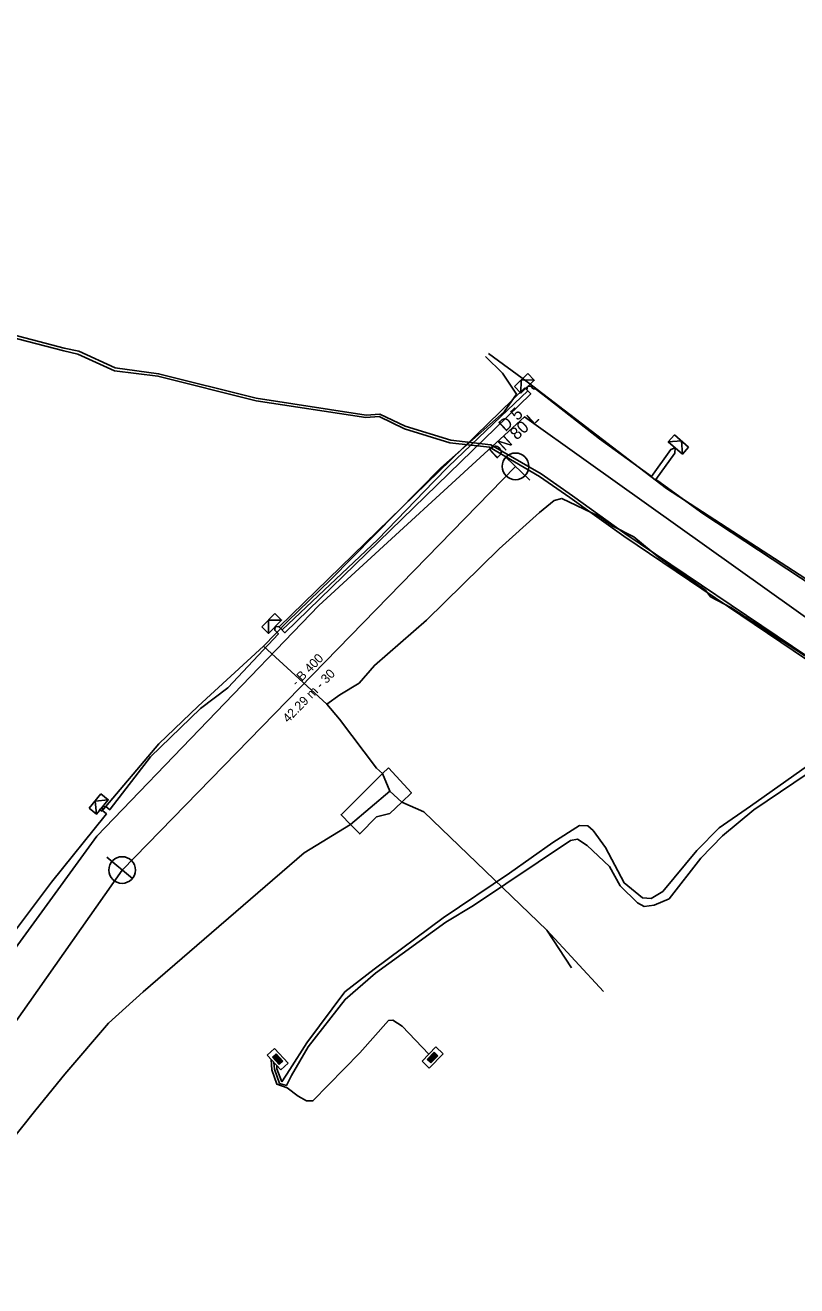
# Model space of a CAD drawing. Extents: x -600636 to -600148, y -1203980 to -1203569.
# Drawn here: x -600483.1 to -600425.2, y -1203834.8 to -1203740.1 of the extents above; entities that cross this region are included whole.
import ezdxf

# ---------------------------------------------------------------- set-up
doc = ezdxf.new("R2010")
doc.units = 0
for name, color, linetype in [('Cetin kolektor kabelovod', 7, 'Continuous'), ('Cetin nezaměřený', 7, 'Continuous'), ('Cetin NN přípojka', 7, 'Continuous'), ('Cetin zam průběh', 7, 'Continuous'), ('EON objekty', 7, 'Continuous'), ('EON podzemní NN', 7, 'Continuous'), ('EON podzemní VN', 7, 'Continuous'), ('Implicitní', 7, 'Continuous'), ('VaK Břeclav_kanalizace', 7, 'Continuous'), ('VaK Břeclav_kanalizace_popis', 7, 'Continuous'), ('Vak Břeclav_vodovod', 7, 'Continuous'), ('Vak Břeclav_vodovod_popis', 7, 'Continuous'), ('Vrstva 9', 7, 'Continuous')]:
    doc.layers.add(name, color=color, linetype=linetype)

# ---------------------------------------------------------------- blocks, each defined once
blk = doc.blocks.new('NN630')
at = {"layer": 'Vrstva 9'}
for points in [[(-0.003, -0.7), (-0.703, 0)], [(-0.703, -0.7), (-0.703, 0), (0.697, 0), (0.697, -0.7)], [(-0.703, -0.7), (0.697, -0.7)], [(-0.003, -0.7), (0.697, 0)]]:
    blk.add_lwpolyline(points, dxfattribs=at)
blk = doc.blocks.new('NN620')
at = {"layer": 'EON objekty'}
for points in [[(0.752, 0.004), (-0.748, 0.004)], [(-0.748, 0.004), (-0.748, -0.746)], [(0.752, -0.746), (0.752, 0.004)], [(-0.748, -0.746), (0.752, -0.746)], [(0.368, -0.18), (-0.376, -0.18)], [(-0.376, -0.18), (-0.376, -0.558)], [(-0.376, -0.558), (0.368, -0.558)], [(0.321, -0.227), (-0.329, -0.227)], [(-0.329, -0.227), (-0.329, -0.51)], [(-0.329, -0.51), (0.321, -0.51)], [(0.274, -0.274), (-0.281, -0.274)], [(-0.281, -0.274), (-0.281, -0.463)], [(-0.281, -0.463), (0.274, -0.463)], [(0.227, -0.321), (-0.234, -0.321)], [(-0.234, -0.321), (-0.234, -0.416)], [(-0.234, -0.416), (0.227, -0.416)], [(-0.193, -0.369), (0.185, -0.369)], [(0.227, -0.416), (0.227, -0.321)], [(0.274, -0.463), (0.274, -0.274)], [(0.321, -0.51), (0.321, -0.227)], [(0.368, -0.558), (0.368, -0.18)]]:
    blk.add_lwpolyline(points, dxfattribs=at)
blk = doc.blocks.new('MoSymbol 2')
at = {"layer": 'Implicitní'}
blk.add_line((0, 0.0005), (0, -0.00075), dxfattribs=at)
blk.add_circle((0, 0), 0.0005, dxfattribs=at)

msp = doc.modelspace()

# ---------------------------------------------------------------- linework, layer by layer
at = {"layer": 'Cetin kolektor kabelovod'}
for points in [[(-600456.27, -1203796.31), (-600456.73, -1203795.91), (-600459.49, -1203792.23)], [(-600454.83, -1203798.45), (-600453.17, -1203799.19), (-600443.93, -1203808.05)], [(-600458.68, -1203800.12), (-600462.14, -1203802.25), (-600474.23, -1203812.68), (-600476.82, -1203815.05), (-600480.09, -1203818.86), (-600482.26, -1203821.55), (-600485.61, -1203825.73), (-600486.63, -1203826.86), (-600489.37, -1203830.16), (-600491.81, -1203833.43)]]:
    msp.add_lwpolyline(points, dxfattribs=at)
msp.add_lwpolyline([(-600455.83, -1203795.87), (-600456.27, -1203796.31), (-600459.37, -1203799.4), (-600458.68, -1203800.12), (-600457.98, -1203800.84), (-600456.71, -1203799.56), (-600455.73, -1203799.3), (-600454.83, -1203798.45), (-600454.1, -1203797.75), (-600455.83, -1203795.87)], close=True, dxfattribs=at)
at = {"layer": 'Cetin nezaměřený'}
for points in [[(-600455.71, -1203797.64), (-600456.27, -1203796.31), (-600456.73, -1203795.91), (-600459.49, -1203792.23)], [(-600455.71, -1203797.64), (-600458.68, -1203800.12), (-600462.14, -1203802.25), (-600474.23, -1203812.68), (-600476.82, -1203815.05), (-600480.09, -1203818.86), (-600482.26, -1203821.55), (-600485.61, -1203825.73), (-600489.37, -1203830.16), (-600491.81, -1203833.43), (-600492.338, -1203834.75)], [(-600455.71, -1203797.64), (-600454.83, -1203798.45), (-600453.17, -1203799.19), (-600443.93, -1203808.05)], [(-600443.93, -1203808.05), (-600439.7, -1203812.67)], [(-600443.93, -1203808.05), (-600442.086, -1203810.898)]]:
    msp.add_lwpolyline(points, dxfattribs=at)
at = {"layer": 'Cetin NN přípojka'}
for points in [[(-600455.71, -1203797.64), (-600458.68, -1203800.12), (-600462.14, -1203802.25), (-600474.23, -1203812.68), (-600476.82, -1203815.05), (-600480.09, -1203818.86), (-600482.26, -1203821.55), (-600485.61, -1203825.73), (-600489.37, -1203830.16), (-600491.81, -1203833.43), (-600492.338, -1203834.75)], [(-600455.71, -1203797.64), (-600454.83, -1203798.45), (-600453.17, -1203799.19), (-600443.93, -1203808.05)], [(-600443.93, -1203808.05), (-600439.7, -1203812.67)]]:
    msp.add_lwpolyline(points, dxfattribs=at)
at = {"layer": 'Cetin zam průběh'}
for points in [[(-600448.32, -1203764.77), (-600445.41, -1203766.9), (-600434.97, -1203774.92), (-600422.32, -1203783.12), (-600413.93, -1203789.04), (-600405.18, -1203794.93), (-600400.25, -1203797.98), (-600398.96, -1203798.36), (-600397.12, -1203797.36), (-600388.96, -1203781.95), (-600378.33, -1203762.13), (-600375.93, -1203758.23), (-600373.1, -1203754.01), (-600370.24, -1203749.96), (-600363.35, -1203740.04), (-600357.38, -1203731.69), (-600349.33, -1203720.15), (-600345.8, -1203715.19), (-600340.07, -1203706.96), (-600329.02, -1203689.27)], [(-600448.55, -1203765.01), (-600447.27, -1203766.25), (-600446.21, -1203767.84)], [(-600446.21, -1203767.84), (-600447.14, -1203769.15), (-600451.9, -1203773.36), (-600460.17, -1203781.78), (-600463.36, -1203784.86)], [(-600447.14, -1203769.15), (-600451.9, -1203773.36)], [(-600460.44, -1203791.11), (-600459.46, -1203790.39), (-600458.03, -1203789.53), (-600456.87, -1203788.19), (-600452.97, -1203784.79), (-600447.51, -1203779.45), (-600444.5, -1203776.72), (-600443.4, -1203775.81), (-600442.82, -1203775.66), (-600440.03, -1203777), (-600438.99, -1203777.73), (-600437.41, -1203778.55), (-600435.55, -1203780.1), (-600432.05, -1203782.55), (-600431.66, -1203783.05), (-600430.13, -1203783.84), (-600423.55, -1203788.15)], [(-600423.55, -1203788.15), (-600430.13, -1203783.84)], [(-600463.36, -1203784.86), (-600465.19, -1203786.74)], [(-600477.51, -1203798.97), (-600477.33, -1203799.12), (-600473.04, -1203794.08), (-600470.1, -1203791.26), (-600465.19, -1203786.74)], [(-600460.44, -1203791.11), (-600465.19, -1203786.74)], [(-600459.49, -1203792.23), (-600460.44, -1203791.11)]]:
    msp.add_lwpolyline(points, dxfattribs=at)
at = {"layer": 'EON podzemní NN'}
for points in [[(-600483.801, -1203808.07), (-600481.102, -1203804.461), (-600477.073, -1203799.464), (-600476.97, -1203799.333), (-600477.249, -1203799.111), (-600477.286, -1203798.816), (-600477.016, -1203798.78), (-600476.722, -1203799.019), (-600476.691, -1203798.98), (-600473.672, -1203795.059), (-600469.91, -1203791.43), (-600467.871, -1203789.879), (-600464.07, -1203785.817), (-600464.347, -1203785.548), (-600464.327, -1203785.286), (-600464.065, -1203785.278), (-600463.799, -1203785.523), (-600456.609, -1203778.75), (-600455.185, -1203777.274), (-600452.407, -1203774.395), (-600451.32, -1203773.27), (-600447.396, -1203769.512), (-600445.375, -1203767.577), (-600445.434, -1203767.516), (-600445.39, -1203767.27), (-600445.152, -1203767.233), (-600444.955, -1203767.436), (-600444.789, -1203767.441), (-600443.789, -1203768.219), (-600439.988, -1203771.191), (-600436.287, -1203773.861), (-600436.095, -1203774), (-600434.65, -1203771.98), (-600434.306, -1203771.872), (-600434.351, -1203772.251), (-600435.77, -1203774.235), (-600435.61, -1203774.35), (-600432.238, -1203776.781), (-600416.559, -1203787.121)], [(-600463.827, -1203819.443), (-600463.215, -1203818.526), (-600461.955, -1203816.525), (-600459.088, -1203812.688), (-600456.905, -1203810.982), (-600451.712, -1203807.127), (-600446.748, -1203803.782), (-600443.481, -1203801.477), (-600441.485, -1203800.213), (-600440.875, -1203800.229), (-600440.465, -1203800.586), (-600439.536, -1203801.867), (-600438.145, -1203804.516), (-600436.76, -1203805.634), (-600436.116, -1203805.68), (-600435.235, -1203805.157), (-600432.692, -1203802.07), (-600431.021, -1203800.385), (-600428.663, -1203798.755), (-600422.759, -1203794.567)], [(-600422.408, -1203794.985), (-600428.406, -1203799.034), (-600430.766, -1203800.969), (-600432.383, -1203802.666), (-600434.772, -1203805.7), (-600435.902, -1203806.189), (-600436.648, -1203806.285), (-600437.15, -1203806.016), (-600438.44, -1203804.723), (-600439.235, -1203803.28), (-600440.923, -1203801.7), (-600441.636, -1203801.236), (-600442.174, -1203801.336), (-600449.439, -1203806.213), (-600451.513, -1203807.458), (-600456.782, -1203811.281), (-600459.079, -1203813.257), (-600461.853, -1203816.815), (-600463.09, -1203818.969), (-600463.48, -1203819.73), (-600464, -1203819.56)], [(-600463.42, -1203819.89), (-600462.6, -1203820.51), (-600461.964, -1203820.858), (-600461.486, -1203820.874), (-600457.959, -1203817.264), (-600455.816, -1203814.832), (-600455.482, -1203814.811), (-600454.791, -1203815.27), (-600452.783, -1203817.366)], [(-600463.42, -1203819.89), (-600464.188, -1203819.627), (-600464.578, -1203818.54), (-600464.624, -1203817.759)], [(-600464, -1203819.56), (-600464.38, -1203818.5), (-600464.41, -1203817.99)], [(-600463.827, -1203819.443), (-600464.182, -1203818.46), (-600464.196, -1203818.225)]]:
    msp.add_lwpolyline(points, dxfattribs=at)
msp.add_lwpolyline([(-600445.584, -1203767.362), (-600445.148, -1203767.811), (-600463.59, -1203785.738), (-600464.026, -1203785.289)], close=True, dxfattribs=at)
at = {"layer": 'EON podzemní VN'}
for points in [[(-600501.847, -1203764.325), (-600497.959, -1203761.475), (-600496.908, -1203761.001), (-600494.282, -1203760.923), (-600480.162, -1203764.577), (-600479.132, -1203764.829), (-600476.382, -1203766.071), (-600473.11, -1203766.482), (-600465.75, -1203768.323), (-600457.511, -1203769.594), (-600456.508, -1203769.518), (-600454.624, -1203770.445), (-600451.211, -1203771.488), (-600448.233, -1203771.815), (-600444.486, -1203774.019), (-600442.217, -1203775.59), (-600438.167, -1203778.496), (-600424.472, -1203787.735), (-600416.801, -1203792.528), (-600411.123, -1203796.487), (-600404.975, -1203801.537), (-600404.82, -1203801.644), (-600404.96, -1203802.62)], [(-600424.36, -1203787.555), (-600438.08, -1203778.28), (-600442.027, -1203775.462), (-600444.357, -1203773.807), (-600448.151, -1203771.631), (-600451.152, -1203771.298), (-600454.57, -1203770.237), (-600456.457, -1203769.325), (-600457.482, -1203769.405), (-600465.732, -1203768.126), (-600473.064, -1203766.298), (-600476.316, -1203765.85), (-600479.036, -1203764.617), (-600480.143, -1203764.381), (-600494.25, -1203760.681)]]:
    msp.add_lwpolyline(points, dxfattribs=at)
at = {"layer": 'VaK Břeclav_kanalizace'}
for p, q in [((-600446.291, -1203773.251), (-600475.798, -1203803.548)), ((-600475.798, -1203803.548), (-600494.416, -1203830.039))]:
    msp.add_line(p, q, dxfattribs=at)
at = {"layer": 'Vak Břeclav_vodovod'}
msp.add_lwpolyline([(-600395.742, -1203804.116), (-600404.972, -1203798.52), (-600440.983, -1203772.83), (-600445.608, -1203769.543), (-600461.034, -1203783.688), (-600477.697, -1203801.016), (-600487.771, -1203814.834)], dxfattribs=at)

# ---------------------------------------------------------------- block references
at = {"layer": 'EON podzemní NN'}
for name, p, rotation in [('NN630', (-600445.39, -1203767.27), -136.2521416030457), ('NN630', (-600434.306, -1203771.872), 139.16664728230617), ('NN630', (-600464.328, -1203785.286), -134.3657555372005), ('NN630', (-600477.287, -1203798.816), -129.28333330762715), ('NN620', (-600464.41, -1203817.99), 132.8438695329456), ('NN620', (-600452.782, -1203817.367), 46.21052774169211)]:
    msp.add_blockref(name, p, dxfattribs=dict(at, rotation=rotation))
at = {"layer": 'VaK Břeclav_kanalizace', "yscale": 1999.7500312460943}
for p, xscale, rotation in [((-600446.291, -1203773.251), 1999.750031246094, 45.75677830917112), ((-600475.798, -1203803.548), 1999.7500312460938, -129.7207282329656)]:
    msp.add_blockref('MoSymbol 2', p, dxfattribs=dict(at, xscale=xscale, rotation=rotation))

# ---------------------------------------------------------------- texts
at = {"layer": 'VaK Břeclav_kanalizace_popis'}
for s, height, p in [('- B 400', 0.6824, (-600462.7, -1203789.817)), ('42.29 m - 30', 0.68241, (-600463.345, -1203792.539))]:
    msp.add_text(s, height=height, rotation=45.75678, dxfattribs=at).set_placement(p)
at = {"layer": 'Vak Břeclav_vodovod_popis'}
for s, p in [('D 5', (-600447.054, -1203770.692)), ('DN 80 L', (-600447.748, -1203772.74))]:
    msp.add_text(s, height=0.9099, rotation=42.51953, dxfattribs=at).set_placement(p)

doc.saveas('drawing.dxf')
